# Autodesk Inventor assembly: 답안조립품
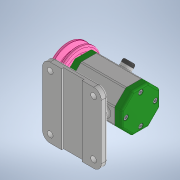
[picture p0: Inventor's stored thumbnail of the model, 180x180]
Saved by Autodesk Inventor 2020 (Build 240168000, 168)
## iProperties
Created: 2022-10
Part Number: 답안조립품
Document SubType Name: Assembly
Designer: USER
Author: USER
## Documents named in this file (16)
- C:\Users\USER\Desktop\721006V1003\답안조립품.iam
- C:\Users\USER\Desktop\721006V1003\1_본체.ipt
- C:\Users\USER\Desktop\721006V1003\V벨트풀리.ipt
- C:\Users\USER\Desktop\721006V1003\고무캡.ipt
- C:\Users\USER\Desktop\721006V1003\너트 M8.ipt
- 너트 M8.ipt
- C:\Users\USER\Desktop\721006V1003\베어링 6002.ipt
- C:\Users\USER\Desktop\721006V1003\볼트 M4x12.ipt
- C:\Users\USER\Desktop\721006V1003\스프링와셔 8.ipt
- C:\Users\USER\Desktop\721006V1003\앞커버.ipt
- C:\Users\USER\Desktop\721006V1003\오일 실 15x25x7.ipt
- C:\Users\USER\Desktop\721006V1003\와셔 8x17.ipt
- C:\Users\USER\Desktop\721006V1003\축.ipt
- C:\Users\USER\Desktop\721006V1003\키 3x3x12.ipt
- 키 3x3x12.ipt
- C:\Users\USER\Desktop\721006V1003\뒤커버.ipt
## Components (3 placed, 3 different names)
1. 1_본체:1
2. V벨트풀리:1
3. 고무캡:1
